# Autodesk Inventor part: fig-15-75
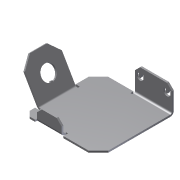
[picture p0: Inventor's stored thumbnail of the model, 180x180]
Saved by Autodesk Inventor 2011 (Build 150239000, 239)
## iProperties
Shininess: 77.0
Angle Display Precision: 2
Document Length Units: 11269
Document Angle Units: 11279
Document Time Units: 11290
Document Mass Units: 11283
Document Length Units Precision: 3
Document Angle Units Precision: 2
Created: 2002-04
Part Number: fig-15-75
Document SubType Name: Sheet Metal
Density: 1 g/cm^3
Sheet Metal Rule: Default
Density: 0.0
Volumn: 0.0
Area: 0.0
PropertySet Name: Model Information
Control State: 0
Master: False
Checked Out: False
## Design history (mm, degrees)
node "Face1"
  sketch "Sketch1"
    geometry: L1 (12.647, 25.882)-(12.647, -14.118); L2 (12.647, -14.118)-(-17.353, -14.118); L3 (-17.353, -14.118)-(-17.353, 15.882); L4 (-17.353, 15.882)-(-2.353, 15.882); L5 (-2.353, 15.882)-(-2.353, 25.882); L6 (-2.353, 25.882)-(12.647, 25.882); 1 further point
    constraints: 12 end point, 4 parallel, 1 perpendicular
    dimensions: "d5" = 30 distance of L2.end L3.end; "d6" = 10 distance of L4.end L5.end; "d7" = 15 distance of L3.end L4.end; "d25" = 15 distance of L5.end L1.start
sketch "Sketch3"
  geometry: L1 (10, -15)-(10, 0)
  constraints: 2 end point
feature "Fold3" sketch "Sketch3" dims "d26" = 0.75 (= BendRadius), "d27" = 90 deg, "d28" = 0.75 (= BendRadius), "d96" = 0.75 (= BendReliefWidth), "d97" = 0.375 (= BendReliefDepth), "d98" = 1.5 (= MinimumRemnant), "SeamGap" = 0.01, "Thickness" = 0.75
node "Flange2"
sketch "Sketch6"
  geometry: L1 (-6.914, 3.413)-(-5.843, 3.413); L2 (-5.843, 0.624)-(-6.914, 0.624); L3 (-6.914, 2.432)-(-5.843, 2.432); L4 (-5.843, 1.605)-(-6.914, 1.605); L5 (-6.914, 0.624)-(-6.914, 1.605); L6 (-6.914, 2.432)-(-6.914, 3.413); L7 (-6.914, 12.568)-(-6.914, 11.587); L8 (-6.914, 14.376)-(-6.914, 13.395); L9 (-6.914, 11.587)-(-5.843, 11.587); L10 (-5.843, 14.376)-(-6.914, 14.376); L11 (-6.914, 12.568)-(-5.843, 12.568); L12 (-5.843, 13.395)-(-6.914, 13.395); A1 r 1.394 centre (-5.843, 2.018) between (-5.843, 0.624) and (-5.843, 3.413); A2 r 0.413 centre (-5.843, 2.018) between (-5.843, 1.605) and (-5.843, 2.432); A3 r 1.394 centre (-5.843, 12.982) between (-5.843, 11.587) and (-5.843, 14.376); A4 r 0.413 centre (-5.843, 12.982) between (-5.843, 12.568) and (-5.843, 13.395)
  constraints: 24 end point, 8 point on circle, 4 centre point, 3 equal length, 1 perpendicular
cut "Cut1" sketch "Sketch6" dims "d49" = 0.75 (= Thickness), "d50" = 0
node "Flange3"
feature "Corner Chamfer1" dims "d70" = 4, "d71" = 4, angle "d105" = 45 deg
feature "Corner Chamfer2" dims "d72" = 2, "d73" = 2, angle "d106" = 45 deg
sketch "Sketch10"
  geometry: 1 further point
feature "iFeature15:3" sketch "Sketch10"
body "Solid1"
face "Plate1" dims "Thickness" = 0.75
sketch "Sketch5"
  geometry: L1 (20, 0)-(5, 0); L2 (5, 0)-(5, 15); L3 (5, 15)-(20, 15); L4 (20, 15)-(20, 0)
  constraints: 8 end point
face "Plate6" dims "d35" = 10, "d36" = 5, "d38" = 15, "d39" = 60 deg, "d40" = 0.75 (= BendRadius), "Thickness" = 0.75, "MinimumRemnant" = 1.5 (= 2 x Thickness), "BendReliefWidth" = 0.75 (= Thickness)
bend "Bend5" dims "d38" = 15, "d39" = 60 deg, "d40" = 0.75 (= BendRadius), "d99" = 0.75 (= BendReliefWidth), "d100" = 0.375 (= BendReliefDepth), "d101" = 1.5 (= MinimumRemnant), "SeamGap" = 0.01, "Thickness" = 0.75, "MinimumRemnant" = 1.5 (= 2 x Thickness), "BendReliefWidth" = 0.75 (= Thickness), "TransitionRadius" = 0.75 (= BendRadius)
sketch "Sketch7"
  geometry: L1 (25, 0)-(15, 0); L2 (15, 0)-(15, 5); L3 (15, 5)-(25, 5); L4 (25, 5)-(25, 0)
  constraints: 8 end point
face "Plate7" dims "d57" = 5, "d58" = 10, "d60" = 5, "d61" = 90 deg, "d62" = 0.75 (= BendRadius), "Thickness" = 0.75, "MinimumRemnant" = 1.5 (= 2 x Thickness), "BendReliefWidth" = 0.75 (= Thickness)
bend "Bend7" dims "d59" = 0.75 (= BendRadius), "d60" = 5, "d61" = 90 deg, "d62" = 0.75 (= BendRadius), "d102" = 0.75 (= BendReliefWidth), "d103" = 0.375 (= BendReliefDepth), "d104" = 1.5 (= MinimumRemnant), "SeamGap" = 0.01, "Thickness" = 0.75, "MinimumRemnant" = 1.5 (= 2 x Thickness), "BendReliefWidth" = 0.75 (= Thickness)
other parameters: "BendRadius" = 0.75 (= Thickness), "BendReliefDepth" = 0.375 (= 0.5 x Thickness), "CornerReliefSize" = 3 (= 4 x Thickness), "d0" = 0.75 (= BendRadius), "d13" = 0.75 (= BendRadius), "d31" = 0.75 (= BendRadius), "d37" = 0.75 (= BendRadius), "d112" = 0, "JacobiRadiusSize" = 0.75 (= Thickness), "GapSize" = 0.75 (= Thickness)
